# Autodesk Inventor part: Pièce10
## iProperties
Shininess: 64.0
Length Units: 11269
Angle Units: 11279
Time Units: 11290
Mass Units: 11283
Length Display Precision: 3
Angle Display Precision: 2
Compacted: True
Part Number: Pièce10
Document SubType Name: Modeling
Created: 2004-06
Material: Par défaut
Designer: laurent
Density: 0.0
Volumn: 0.0
Area: 0.0
PropertySet Name: Model Information
Control State: 0
Master: False
Checked Out: False
Author: laurent
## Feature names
1. Révolution1 [Revolution]
2. Extrusion1
